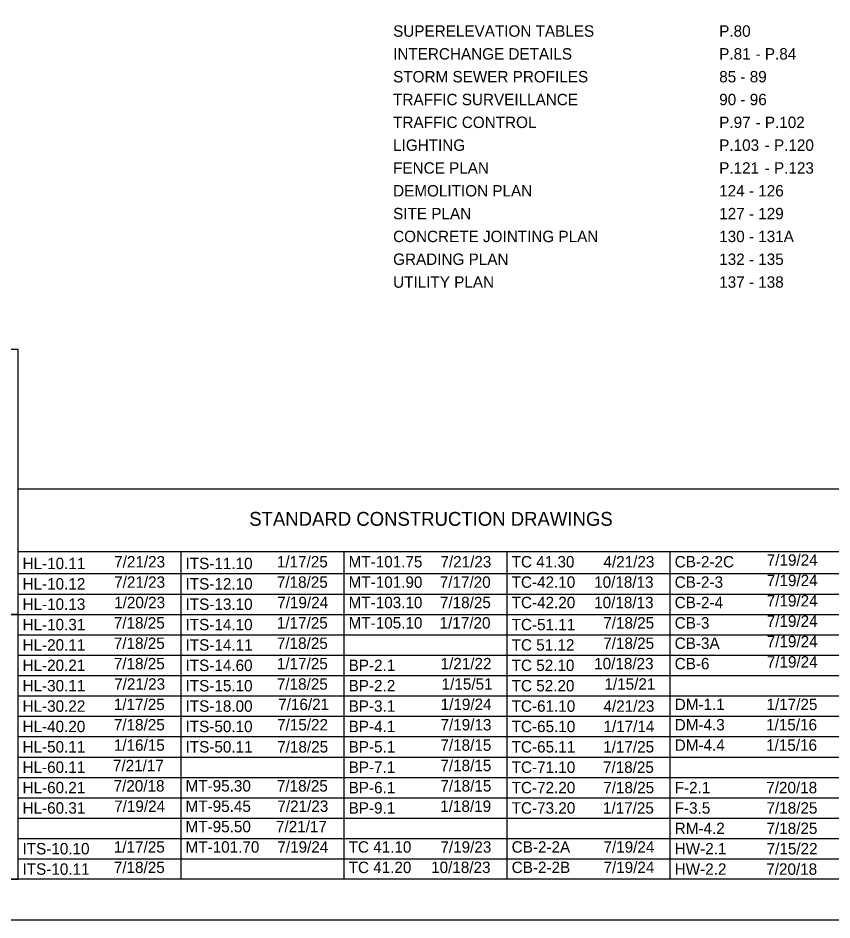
# Model space of a CAD drawing. Extents: x -21.9 to 47.3, y 14.1 to 48.7.
# Drawn here: x 10.15 to 20.13, y 26.73 to 37.8 of the extents above; entities that cross this region are included whole.
import ezdxf

# ---------------------------------------------------------------- set-up
doc = ezdxf.new("R2010")
doc.units = 0
for name, color, linetype in [('SH_Border', 7, 'Continuous'), ('SH_Cut_Line', 7, 'Continuous'), ('SH_Data', 7, 'Continuous'), ('SH_Text', 7, 'Continuous')]:
    doc.layers.add(name, color=color, linetype=linetype)

msp = doc.modelspace()

# ---------------------------------------------------------------- linework, layer by layer
at = {"layer": 'SH_Border'}
msp.add_lwpolyline([(1.5, 48.233), (33.5, 48.233), (33.5, 27.233), (1.5, 27.233)], close=True, dxfattribs=at)
at = {"layer": 'SH_Cut_Line'}
msp.add_lwpolyline([(0, 26.733), (34, 26.733), (34, 48.733), (0, 48.733)], close=True, dxfattribs=at)
at = {"layer": 'SH_Data'}
for p, q in [((10.15, 32.025), (23.6, 32.025)), ((10.15, 27.233), (10.15, 32.025)), ((10.15, 31.254), (23.6, 31.254)), ((12.15, 27.233), (12.15, 31.254)), ((14.15, 27.233), (14.15, 31.254)), ((16.15, 27.233), (16.15, 31.254)), ((18.15, 27.233), (18.15, 31.254)), ((10.15, 30.983), (23.6, 30.983)), ((10.15, 30.733), (23.6, 30.733)), ((10.15, 30.483), (23.6, 30.483)), ((10.15, 30.233), (23.6, 30.233)), ((10.15, 29.983), (23.6, 29.983)), ((10.15, 29.733), (23.6, 29.733)), ((10.15, 29.483), (23.6, 29.483)), ((10.15, 29.233), (23.6, 29.233)), ((10.15, 28.983), (23.6, 28.983)), ((10.15, 28.733), (23.6, 28.733)), ((10.15, 28.483), (23.6, 28.483)), ((10.15, 28.233), (23.6, 28.233)), ((10.15, 27.983), (23.6, 27.983)), ((10.15, 27.733), (23.6, 27.733)), ((10.15, 27.483), (23.6, 27.483))]:
    msp.add_line(p, q, dxfattribs=at)
for points in [[(10.15, 33.733), (7.35, 33.733), (7.35, 30.483), (10.15, 30.483)], [(10.15, 30.483), (7.35, 30.483), (7.35, 27.233), (10.15, 27.233)]]:
    msp.add_lwpolyline(points, close=True, dxfattribs=at)

# ---------------------------------------------------------------- texts
at = {"layer": 'SH_Text'}
for s, height, p in [('SUPERELEVATION TABLES', 0.14, (14.751, 37.571)), ('P.80', 0.14, (18.751, 37.571)), ('INTERCHANGE DETAILS', 0.14, (14.751, 37.291)), ('P.81', 0.14, (18.751, 37.291)), ('P.84', 0.14, (19.311, 37.291)), (' - ', 0.14, (19.144, 37.291)), ('STORM SEWER PROFILES', 0.14, (14.751, 37.011)), ('85 - 89', 0.14, (18.751, 37.011)), ('TRAFFIC SURVEILLANCE', 0.14, (14.751, 36.731)), ('90 - 96', 0.14, (18.751, 36.731)), ('TRAFFIC CONTROL', 0.14, (14.751, 36.451)), ('P.97', 0.14, (18.751, 36.451)), ('P.102', 0.14, (19.311, 36.451)), (' - ', 0.14, (19.144, 36.451)), ('LIGHTING', 0.14, (14.751, 36.171)), ('P.103', 0.14, (18.751, 36.171)), ('P.120', 0.14, (19.423, 36.171)), (' - ', 0.14, (19.256, 36.171)), ('FENCE PLAN', 0.14, (14.751, 35.891)), ('P.121', 0.14, (18.751, 35.891)), ('P.123', 0.14, (19.423, 35.891)), (' - ', 0.14, (19.256, 35.891)), ('DEMOLITION PLAN', 0.14, (14.751, 35.611)), ('124 - 126', 0.14, (18.751, 35.611)), ('SITE PLAN', 0.14, (14.751, 35.331)), ('127 - 129', 0.14, (18.751, 35.331)), ('CONCRETE JOINTING PLAN', 0.14, (14.751, 35.051)), ('130 - 131A', 0.14, (18.751, 35.051)), ('GRADING PLAN', 0.14, (14.751, 34.771)), ('132 - 135', 0.14, (18.751, 34.771)), ('UTILITY PLAN', 0.14, (14.751, 34.491)), ('137 - 138', 0.14, (18.751, 34.491)), ('STANDARD CONSTRUCTION DRAWINGS', 0.17, (12.986, 31.57)), (' 7/19/24', 0.14, (19.282, 31.08)), ('HL-10.11', 0.14, (10.205, 31.038)), ('7/21/23', 0.14, (11.329, 31.059)), ('ITS-11.10', 0.14, (12.205, 31.038)), ('1/17/25', 0.14, (13.325, 31.059)), ('MT-101.75', 0.14, (14.205, 31.059)), (' 7/21/23', 0.14, (15.279, 31.059)), ('TC 41.30 ', 0.14, (16.205, 31.059)), (' 4/21/23', 0.14, (17.279, 31.059)), ('CB-2-2C  ', 0.14, (18.205, 31.059)), ('HL-10.12', 0.14, (10.205, 30.788)), ('7/21/23', 0.14, (11.329, 30.809)), ('ITS-12.10', 0.14, (12.205, 30.788)), ('7/18/25', 0.14, (13.325, 30.809)), ('MT-101.90', 0.14, (14.205, 30.809)), (' 7/17/20', 0.14, (15.271, 30.809)), ('TC-42.10', 0.14, (16.205, 30.809)), ('10/18/13', 0.14, (17.217, 30.809)), ('CB-2-3   ', 0.14, (18.205, 30.809)), (' 7/19/24', 0.14, (19.282, 30.83)), ('HL-10.13', 0.14, (10.205, 30.538)), ('1/20/23', 0.14, (11.329, 30.559)), ('ITS-13.10', 0.14, (12.205, 30.538)), ('7/19/24', 0.14, (13.329, 30.559)), ('MT-103.10', 0.14, (14.205, 30.559)), ('7/18/25', 0.14, (15.325, 30.559)), ('TC-42.20', 0.14, (16.205, 30.559)), ('10/18/13', 0.14, (17.217, 30.559)), ('CB-2-4   ', 0.14, (18.205, 30.559)), (' 7/19/24', 0.14, (19.282, 30.58)), ('7/18/25', 0.14, (11.325, 30.309)), ('1/17/25', 0.14, (13.325, 30.309)), ('MT-105.10', 0.14, (14.205, 30.309)), ('1/17/20', 0.14, (15.321, 30.309)), (' 7/18/25', 0.14, (17.276, 30.309)), ('CB-3     ', 0.14, (18.205, 30.309)), (' 7/19/24', 0.14, (19.282, 30.33)), ('HL-10.31', 0.14, (10.205, 30.288)), ('ITS-14.10', 0.14, (12.205, 30.288)), ('TC-51.11', 0.14, (16.205, 30.288)), (' 7/19/24', 0.14, (19.282, 30.08)), ('HL-20.11', 0.14, (10.205, 30.038)), ('7/18/25', 0.14, (11.325, 30.059)), ('ITS-14.11', 0.14, (12.205, 30.038)), ('7/18/25', 0.14, (13.325, 30.059)), ('TC 51.12 ', 0.14, (16.205, 30.038)), (' 7/18/25', 0.14, (17.276, 30.059)), ('CB-3A    ', 0.14, (18.205, 30.059)), ('HL-20.21', 0.14, (10.205, 29.788)), ('7/18/25', 0.14, (11.325, 29.809)), ('ITS-14.60', 0.14, (12.205, 29.788)), ('1/17/25', 0.14, (13.325, 29.809)), ('BP-2.1   ', 0.14, (14.205, 29.788)), (' 1/21/22', 0.14, (15.281, 29.809)), ('TC 52.10 ', 0.14, (16.205, 29.788)), ('10/18/23', 0.14, (17.217, 29.809)), ('CB-6     ', 0.14, (18.205, 29.809)), (' 7/19/24', 0.14, (19.282, 29.83)), ('HL-30.11 ', 0.14, (10.205, 29.538)), ('7/21/23', 0.14, (11.329, 29.559)), ('ITS-15.10', 0.14, (12.205, 29.538)), ('7/18/25', 0.14, (13.325, 29.559)), ('BP-2.2   ', 0.14, (14.205, 29.538)), (' 1/15/51', 0.14, (15.294, 29.559)), ('TC 52.20 ', 0.14, (16.205, 29.538)), (' 1/15/21', 0.14, (17.291, 29.559)), ('1/17/25', 0.14, (11.325, 29.309)), ('7/16/21', 0.14, (13.341, 29.309)), (' 1/19/24', 0.14, (15.282, 29.309)), ('DM-1.1   ', 0.14, (18.205, 29.309)), (' 1/17/25', 0.14, (19.279, 29.309)), ('HL-30.22 ', 0.14, (10.205, 29.288)), ('ITS-18.00', 0.14, (12.205, 29.288)), ('BP-3.1   ', 0.14, (14.205, 29.288)), ('TC-61.10 ', 0.14, (16.205, 29.288)), (' 4/21/23', 0.14, (17.279, 29.288)), ('HL-40.20', 0.14, (10.205, 29.038)), ('7/18/25', 0.14, (11.325, 29.059)), ('ITS-50.10', 0.14, (12.205, 29.038)), ('7/15/22', 0.14, (13.328, 29.059)), ('BP-4.1', 0.14, (14.205, 29.038)), ('7/19/13', 0.14, (15.332, 29.059)), ('TC-65.10 ', 0.14, (16.205, 29.038)), (' 1/17/14', 0.14, (17.279, 29.038)), ('DM-4.3   ', 0.14, (18.205, 29.059)), (' 1/15/16', 0.14, (19.274, 29.059)), ('HL-50.11', 0.14, (10.205, 28.788)), ('1/16/15', 0.14, (11.325, 28.809)), ('ITS-50.11', 0.14, (12.205, 28.788)), ('7/18/25', 0.14, (13.329, 28.788)), ('BP-5.1   ', 0.14, (14.205, 28.788)), (' 7/18/15', 0.14, (15.279, 28.809)), ('TC-65.11 ', 0.14, (16.205, 28.788)), (' 1/17/25', 0.14, (17.276, 28.788)), ('DM-4.4   ', 0.14, (18.205, 28.809)), (' 1/15/16', 0.14, (19.274, 28.809)), ('HL-60.11', 0.14, (10.205, 28.538)), ('7/21/17', 0.14, (11.314, 28.559)), ('BP-7.1', 0.14, (14.205, 28.538)), (' 7/18/15', 0.14, (15.279, 28.559)), ('TC-71.10', 0.14, (16.205, 28.538)), ('7/18/25', 0.14, (17.325, 28.538)), ('7/20/18', 0.14, (11.322, 28.309)), ('MT-95.30', 0.14, (12.205, 28.309)), ('7/18/25', 0.14, (13.325, 28.309)), (' 7/18/15', 0.14, (15.279, 28.309)), ('HL-60.21', 0.14, (10.205, 28.288)), ('BP-6.1   ', 0.14, (14.205, 28.288)), ('TC-72.20 ', 0.14, (16.205, 28.288)), (' 7/18/25', 0.14, (17.276, 28.288)), ('F-2.1    ', 0.14, (18.205, 28.288)), (' 7/20/18', 0.14, (19.276, 28.288)), ('HL-60.31', 0.14, (10.205, 28.038)), ('7/19/24', 0.14, (11.329, 28.059)), ('MT-95.45 ', 0.14, (12.205, 28.059)), (' 7/21/23', 0.14, (13.279, 28.059)), ('BP-9.1   ', 0.14, (14.205, 28.038)), (' 1/18/19', 0.14, (15.277, 28.059)), ('TC-73.20', 0.14, (16.205, 28.038)), ('1/17/25', 0.14, (17.325, 28.038)), ('F-3.5    ', 0.14, (18.205, 28.038)), (' 7/18/25', 0.14, (19.279, 28.038)), ('MT-95.50', 0.14, (12.205, 27.809)), ('7/21/17', 0.14, (13.314, 27.809)), ('RM-4.2   ', 0.14, (18.205, 27.788)), (' 7/18/25', 0.14, (19.279, 27.788)), ('ITS-10.10', 0.14, (10.205, 27.538)), ('1/17/25', 0.14, (11.325, 27.559)), ('MT-101.70', 0.14, (12.205, 27.559)), (' 7/19/24', 0.14, (13.279, 27.559)), ('TC 41.10 ', 0.14, (14.205, 27.559)), (' 7/19/23', 0.14, (15.279, 27.559)), ('CB-2-2A  ', 0.14, (16.205, 27.559)), (' 7/19/24', 0.14, (17.279, 27.559)), ('HW-2.1', 0.14, (18.205, 27.538)), (' 7/15/22', 0.14, (19.281, 27.538)), ('7/18/25', 0.14, (11.325, 27.309)), ('TC 41.20 ', 0.14, (14.205, 27.309)), ('10/18/23', 0.14, (15.217, 27.309)), ('CB-2-2B  ', 0.14, (16.205, 27.309)), (' 7/19/24', 0.14, (17.279, 27.309)), ('ITS-10.11', 0.14, (10.205, 27.288)), ('HW-2.2', 0.14, (18.205, 27.288)), (' 7/20/18', 0.14, (19.276, 27.288))]:
    msp.add_text(s, height=height, dxfattribs=at).set_placement(p)

doc.saveas('drawing.dxf')
